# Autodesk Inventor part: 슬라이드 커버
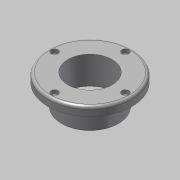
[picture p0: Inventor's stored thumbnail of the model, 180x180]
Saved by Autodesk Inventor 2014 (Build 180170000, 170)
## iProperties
Created: 2015-10
Part Number: 슬라이드 커버
Document SubType Name: Modeling
Designer: mdu
Density: 7.86 g/cm^3
Material: 강철, 연강
Mass: 633.012 g
Surface Area: 239.629 cm^2
Volume: 80.5358 cm^3
Appearance: 강철
Author: mdu
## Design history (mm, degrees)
sketch "스케치1"
  geometry: C1 r 47.5 at (0, 0); C2 r 32.5 at (0, 0); 1 further point
  constraints: 2 centre point, 2 coincident
  dimensions: "d33" = 95 diameter of C1; "d35" = 65 diameter of C2
extrude "돌출1" new body sketch "스케치1" distance "d0" = 10; taper "d1" = 0 deg
extrude "돌출2" join sketch "스케치1" distance "d2" = 25; taper "d3" = 0 deg
hole "구멍1" diameter "d6" = 50; stored, may be unused: countersink angle "d10" = 90 deg, drill point angle "d12" = 118 deg; dims "d4" = 10, "d5" = 10, "d7" = 6, "d8" = 4, "d9" = 2, "d11" = 8
sketch "스케치2" dims "d36" = 80
  geometry: 4 further points
  constraints: 2 coincident, 2 vertical alignment, 2 other
hole "구멍2" sketch "스케치2" at (0, 40) diameter "d13" = 4.5; stored, may be unused: countersink angle "d17" = 90 deg, drill point angle "d19" = 118 deg; dims "d14" = 6, "d15" = 8, "d16" = 4.4, "d18" = 8
fillet "모깎기1" dims "d23" = 3
chamfer "모따기1" distance "d24" = 1; stored, may be unused: second distance "d25" = 2, angle "d26" = 45 deg
sketch "스케치3"
  geometry: C1 r 25 at (0, 0); C2 r 30 at (0, 0); C3 r 26 at (0, 0) reference; 1 further point
  constraints: 2 centre point, 2 coincident
  dimensions: "d27" = 60 diameter of C2
extrude "돌출3" cut sketch "스케치3" distance "d28" = 3; taper "d29" = 0 deg
chamfer "모따기2" distance "d30" = 1; stored, may be unused: second distance "d31" = 2, angle "d32" = 45 deg
node "솔리드1"
pattern_circular "원형 패턴1" dims angle "d21" = 360 deg
